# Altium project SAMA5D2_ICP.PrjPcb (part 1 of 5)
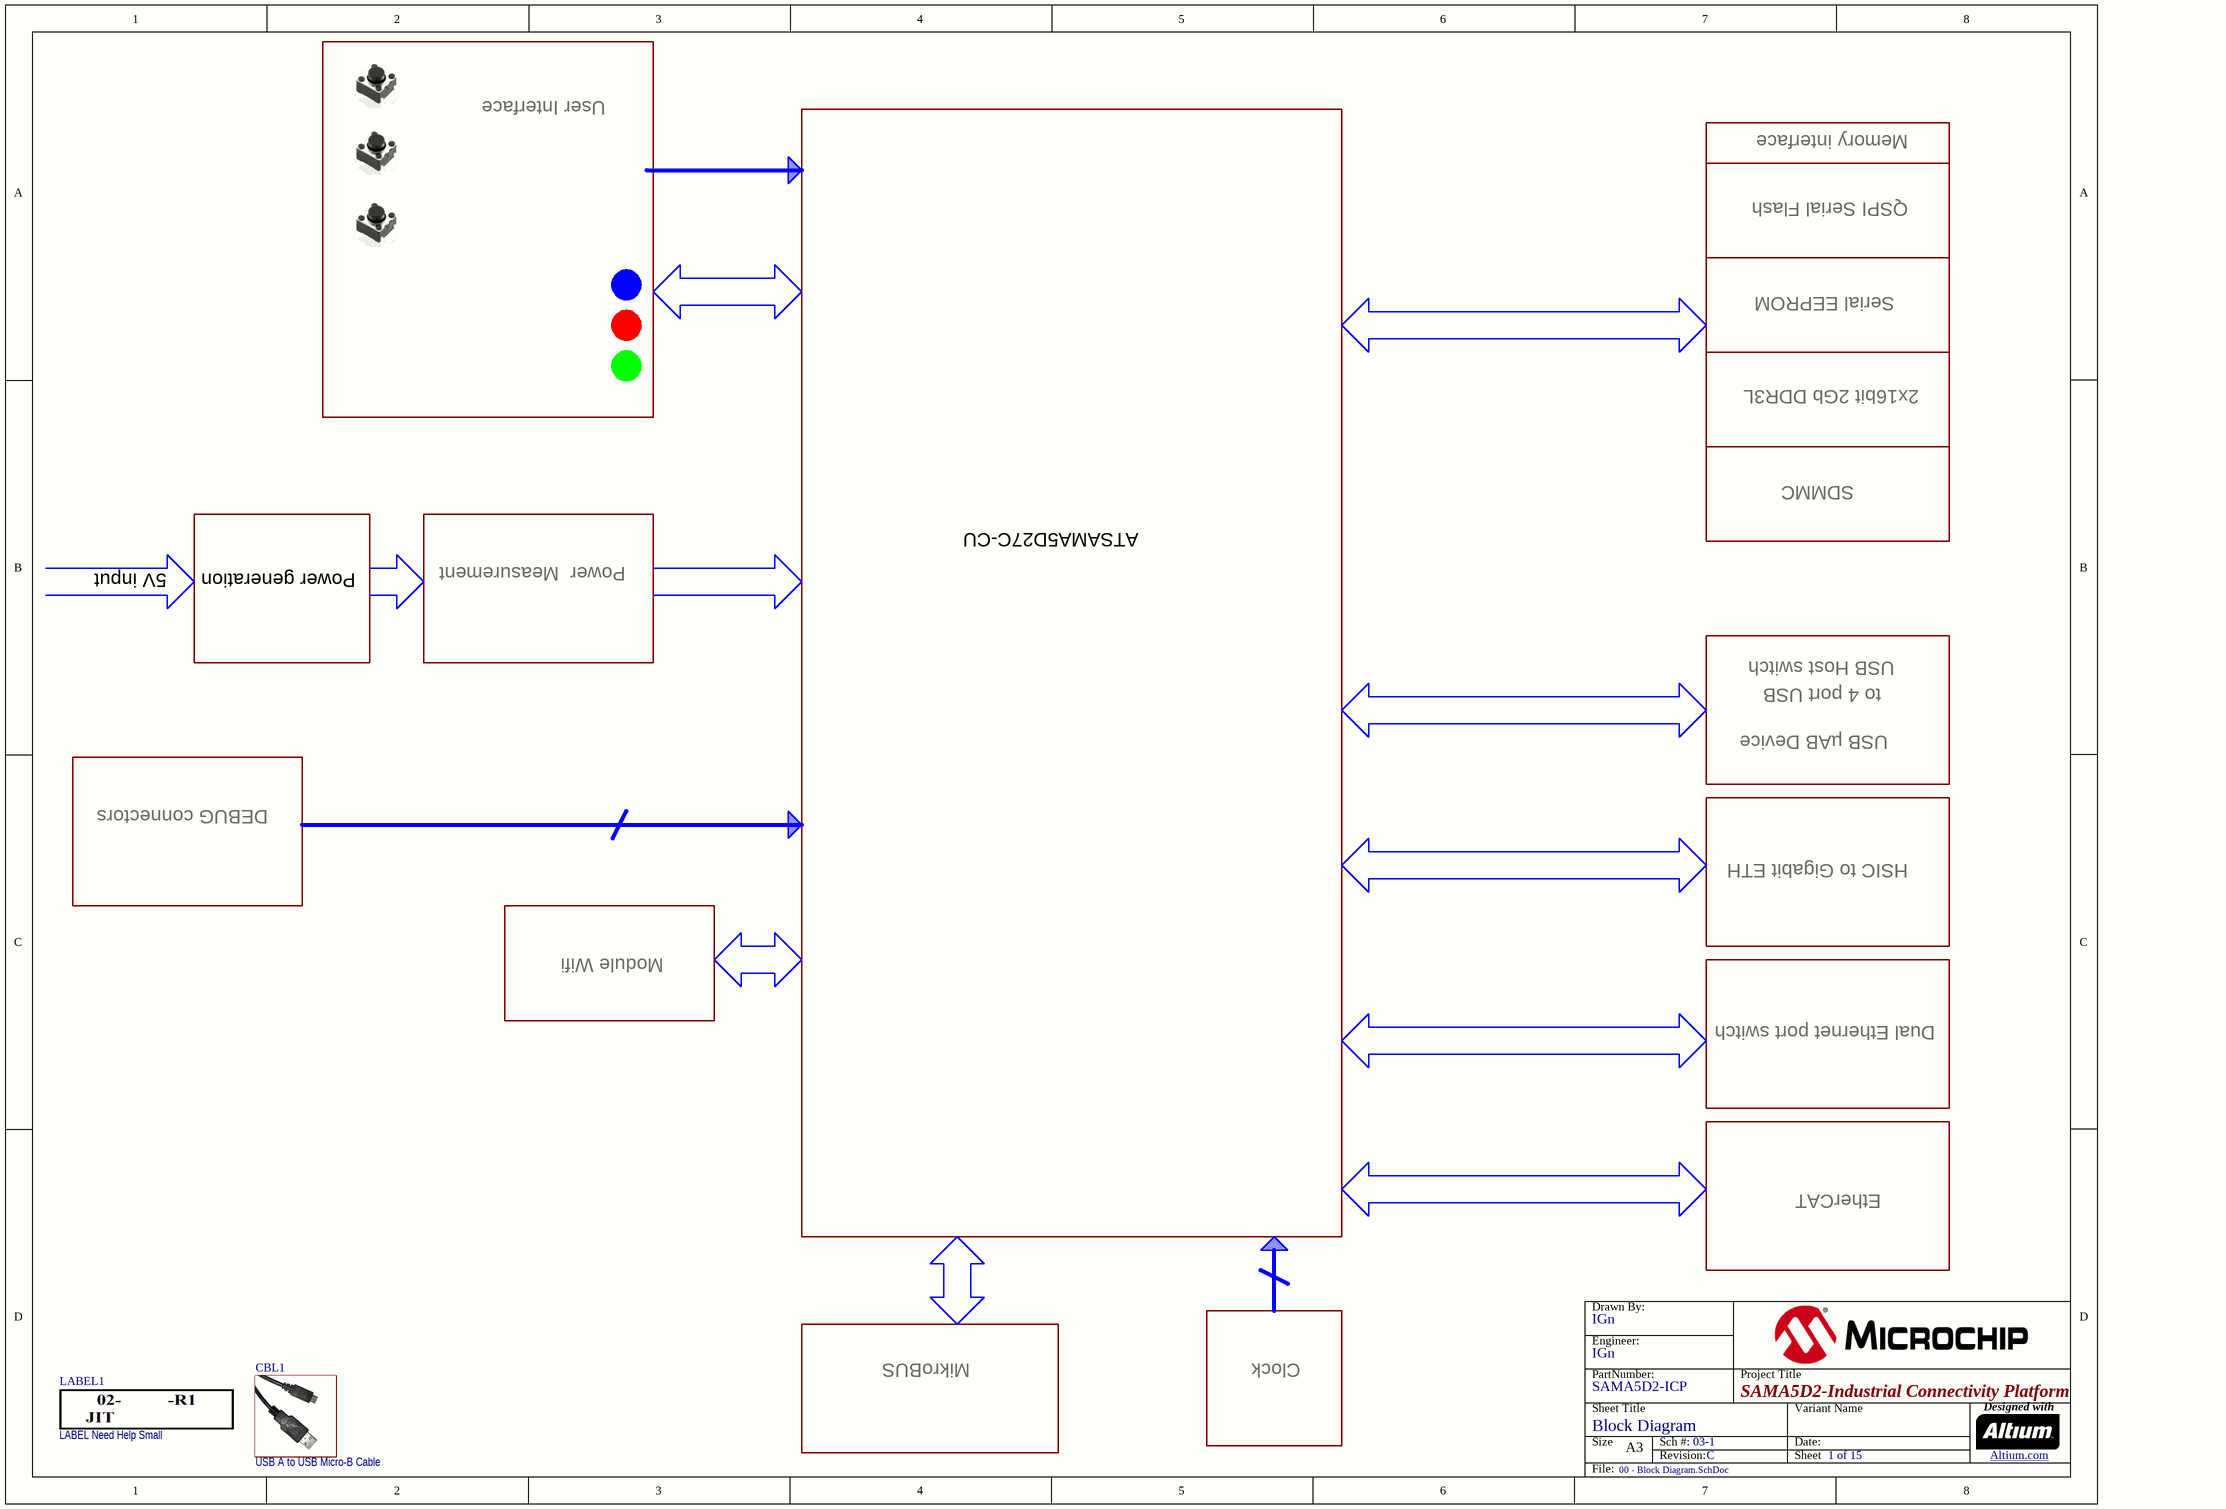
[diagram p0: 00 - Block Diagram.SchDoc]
ProjectBoardNumber: 1; ProjectDrawnBy: IGn; ProjectEngineer: IGn; ProjectPartNumber: SAMA5D2-ICP; ProjectRevisionART: C; ProjectRevisionASSY: C; ProjectRevisionFAB: C; ProjectRevisionSCH: C; ProjectTitle: SAMA5D2-Industrial Connectivity Platform
15 sheets, 727 parts. Net scope: global (net labels, ports and power ports of the same name join across sheets).
Board file: SAMA5D2_ICP.PcbDoc
Sheets:
  00 - Block Diagram.SchDoc
  01 - Power Supply.SchDoc
  02 - Power Measurement.SchDoc
  03 - SAMA5D2 - MPU.SchDoc
  04 - SAMA5D2 - DDR.SchDoc
  05 - SAMA5D2 - PIOs.SchDoc
  06 - USB.SchDoc
  07 - USB HSIC to Gb Ethernet.SchDoc
  08 - Ethernet switch.SchDoc
  09 - EtherCAT interface.SchDoc
  10 - CAN & WiFi BT.SchDoc
  11 - On Board Memories.SchDoc
  12 - Expansion connectors.SchDoc
  13 - User Command & Control.SchDoc
  14 - JLINK-OB Interface.SchDoc

## Sheet 00 - Block Diagram.SchDoc
size A3; CompanyName: Microchip Technology Inc.; Organization: Microchip Technology; Address1: 2355 West Chandler Blvd.; Address2: Chandler, AZ  85224; Address4: USA; DocumentNumber: 1; SheetNumber: 1; SheetTotal: 15; SheetTitle: Block Diagram

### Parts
(Parts that share a designator on the sheet are numbered #1, #2 ... from top to bottom, then left to right.)
?#1  (no value)  (graphical)
CBL1  USB A to USB Micro-B Cable  (mechanical)
LABEL1  value LABEL Need Help Small  [LABEL_Need_Help_Small]  (hidden comment: LABEL_Need_Help_Small)

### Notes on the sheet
- User Interface
- Memory interface
- QSPI Serial Flash
- Serial EEPROM
- 2x16bit 2Gb DDR3L
- SDMMC
- 5V input
- Power generation
- Power  Measurement
- ATSAMA5D27C-CU
- USB Host switch
- to 4 port USB
- USB µAB Device
- DEBUG connectors
- HSIC to Gigabit ETH
- Module Wifi
- Dual Ethernet port switch
- EtherCAT
- MikroBUS
- Clock

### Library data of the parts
?#1 = Title Block A3
CBL1 = CAB1020: Manufacturer 1: Assmann WSW Components; Manufacturer Part Number 1: AK67421-1; Description_: MECH HW CABLE USB Male A TO USB Male Micro-B 1M; Dev Tools Status: Design; Owner: Ilie Galan; Populated: MECH
LABEL1 = 08-00028: Description_: LABEL, ASSY W/REV LEVEL (SMALL MODULES) PER MTS-0002; Dev Tools Status: Production; Populated: MECH

## Sheet 01 - Power Supply.SchDoc
size B; CompanyName: Microchip Technology Inc.; Organization: Microchip Technology; Address1: 2355 West Chandler Blvd.; Address2: Chandler, AZ  85224; Address4: USA; DocumentNumber: 2; SheetNumber: 2; SheetTotal: 15; SheetTitle: Power Supply
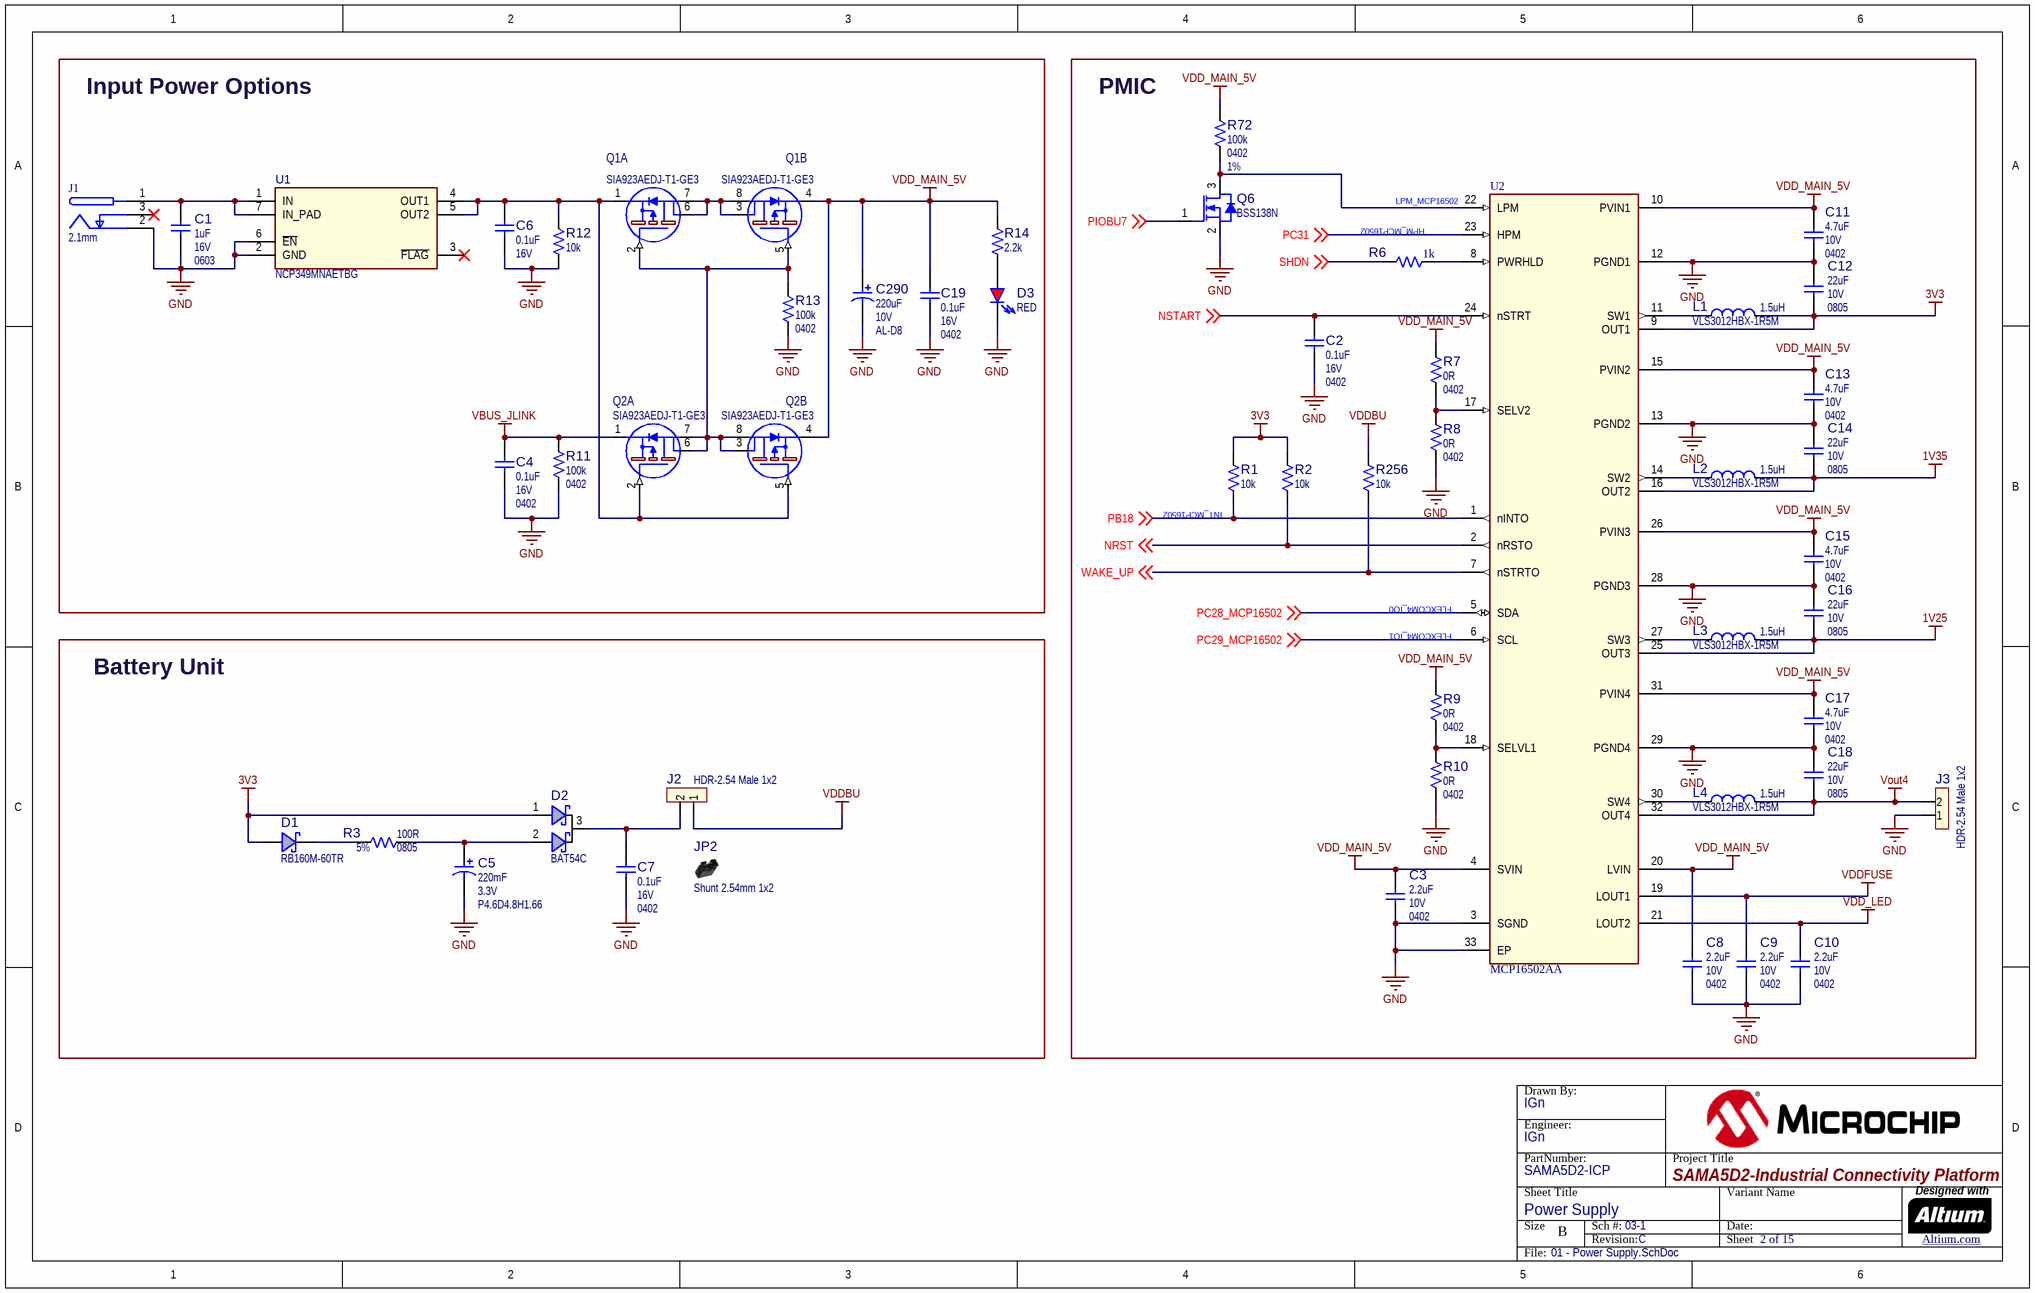
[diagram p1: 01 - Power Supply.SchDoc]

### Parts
(Parts that share a designator on the sheet are numbered #1, #2 ... from top to bottom, then left to right.)
?#2  (no value)  (graphical)
C1  value 1uF  Voltage: 16V  Package: 0603  [CAP_C_0603]  (hidden comment: Capacitor NP)
C2  value 0.1uF  Voltage: 16V  Package: 0402  [CAP_C_0402]  (hidden comment: Capacitor NP)
C3  value 2.2uF  Voltage: 10V  Package: 0402  [CAP_C_0402]  (hidden comment: Capacitor NP)
C4  value 0.1uF  Voltage: 16V  Package: 0402  [CAP_C_0402]  (hidden comment: Capacitor NP)
C5  value 220mF  Voltage: 3.3V  Package: P4.6D4.8H1.66  [CAP_SMD_ECH-U1C471JX5]  (hidden comment: Capacitor POL)
C6  value 0.1uF  Voltage: 16V  [CAP_C_0402]  (hidden comment: Capacitor NP)
C7  value 0.1uF  Voltage: 16V  Package: 0402  [CAP_C_0402]  (hidden comment: Capacitor NP)
C8  value 2.2uF  Voltage: 10V  Package: 0402  [CAP_C_0402]  (hidden comment: Capacitor NP)
C9  value 2.2uF  Voltage: 10V  Package: 0402  [CAP_C_0402]  (hidden comment: Capacitor NP)
C10  value 2.2uF  Voltage: 10V  Package: 0402  [CAP_C_0402]  (hidden comment: Capacitor NP)
C11  value 4.7uF  Voltage: 10V  Package: 0402  [CAP_C_0402]  (hidden comment: Capacitor NP)
C12  value 22uF  Voltage: 10V  Package: 0805  [CAP_C_0805]  (hidden comment: Capacitor NP)
C13  value 4.7uF  Voltage: 10V  Package: 0402  [CAP_C_0402]  (hidden comment: Capacitor NP)
C14  value 22uF  Voltage: 10V  Package: 0805  [CAP_C_0805]  (hidden comment: Capacitor NP)
C15  value 4.7uF  Voltage: 10V  Package: 0402  [CAP_C_0402]  (hidden comment: Capacitor NP)
C16  value 22uF  Voltage: 10V  Package: 0805  [CAP_C_0805]  (hidden comment: Capacitor NP)
C17  value 4.7uF  Voltage: 10V  Package: 0402  [CAP_C_0402]  (hidden comment: Capacitor NP)
C18  value 22uF  Voltage: 10V  Package: 0805  [CAP_C_0805]  (hidden comment: Capacitor NP)
C19  value 0.1uF  Voltage: 16V  Package: 0402  [CAP_C_0402]  (hidden comment: Capacitor NP)
C290  value 220uF  Voltage: 10V  Package: AL-D8  [CAP_AL_D8]  (hidden comment: Capacitor POL)
D1  value RB160M-60TR  [SOD-123FL]  (hidden comment: Diode Schottky)
D2  value BAT54C  [SOT-23-3]  (hidden comment: Diode Schottky Dual CK)
D3  value RED  [LED_0402_RED]  (hidden comment: LED_red)
J1  value 2.1mm  [CON_JACK_POWER_TH_RA_MPD_EJ508A]  (hidden comment: CON JACK 2C 3P SPST)
J2  value HDR-2.54 Male 1x2  [HDR_M_2.54_1x2]  (hidden comment: Header 1x2)
J3  value HDR-2.54 Male 1x2  [HDR_M_2.54_1x2]  (hidden comment: Header 1x2)
JP2  value Shunt 2.54mm 1x2  [Jumper_Mechanical]  (hidden comment: Jumper Mechanical)  (mechanical)
L1  value 1.5uH  Manufacturer Part Number 1: VLS3012HBX-1R5M  [IND_C_1212]  (hidden comment: Inductor)
L2  value 1.5uH  Manufacturer Part Number 1: VLS3012HBX-1R5M  [IND_C_1212]  (hidden comment: Inductor)
L3  value 1.5uH  Manufacturer Part Number 1: VLS3012HBX-1R5M  [IND_C_1212]  (hidden comment: Inductor)
L4  value 1.5uH  Manufacturer Part Number 1: VLS3012HBX-1R5M  [IND_C_1212]  (hidden comment: Inductor)
Q1  SIA923AEDJ-T1-GE3  [SiA923AEDJ PPAK_SC70_6L]  (parts A,B of 2)
Q2  SIA923AEDJ-T1-GE3  [SiA923AEDJ PPAK_SC70_6L]  (parts A,B of 2)
Q6  value BSS138N  [SOT-23-3]  (hidden comment: Transistor MOS-N GSD)
R1  value 10k  [RES_C_0402]  (hidden comment: Resistor)
R2  value 10k  [RES_C_0402]  (hidden comment: Resistor)
R3  value 100R  Package: 0805  Tolerance: 5%  [RES_C_0805]  (hidden comment: Resistor)
R6  value 1k  [RES_C_0603]  (hidden comment: Resistor)
R7  value 0R  Package: 0402  [RES_C_0402]  (hidden comment: Resistor)
R8  value 0R  Package: 0402  [RES_C_0402]  (hidden comment: Resistor)
R9  value 0R  Package: 0402  [RES_C_0402]  (hidden comment: Resistor)
R10  value 0R  Package: 0402  [RES_C_0402]  (hidden comment: Resistor)
R11  value 100k  Package: 0402  [RES_C_0402]  (hidden comment: Resistor)
R12  value 10k  [RES_C_0402]  (hidden comment: Resistor)
R13  value 100k  Package: 0402  [RES_C_0402]  (hidden comment: Resistor)
R14  value 2.2k  [RES_C_0603]  (hidden comment: Resistor)
R72  value 100k  Package: 0402  Tolerance: 1%  [RES_C_0402]  (hidden comment: Resistor)
R256  value 10k  [RES_C_0402]  (hidden comment: Resistor)
U1  value NCP349MNAETBG  [DFN-6_2x1.6_EP0.4x0.35]  (hidden comment: NCP349 DFN-6)
U2  MCP16502AA  [QFN-32_5X5_EP3.7X3.7]

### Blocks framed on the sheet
Input Power Options: C1 C4 C6 C19 C290 D3 J1 Q1 Q2 R11-R14 U1
PMIC: C2 C3 C8-C18 J3 L1-L4 Q6 R1 R2 R6-R10 R72 R256 U2
Battery Unit: C5 C7 D1 D2 J2 JP2 R3

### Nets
1V25: C16.1 L3.2(F) U2.25(OUT3)
1V35: C14.1 L2.2(F) U2.16(OUT2)
3V3: C12.1 D1.1(A) D2.1(A) L1.2(F) R1.2 R2.2 U2.9(OUT1)
GND: C1.1 C2.1 C3.1 C4.1 C5.2 C6.1 C7.1 C8.1 C9.1 C10.1 C11.1 C12.2 C13.1 C14.2 C15.1 C16.2 C17.1 C18.2 C19.1 C290.2 D3.2(K) J1.2(COM) J3.1 Q6.2(S) R8.1 R10.1 R11.2 R12.1 R13.2 U1.2(GND) U1.6(~{EN}) U2.3(SGND) U2.12(PGND1) U2.13(PGND2) U2.28(PGND3) U2.29(PGND4) U2.33(EP)
VBUS_JLINK: C4.2 Q2.1(S1) R11.1
VDD_LED: C10.2 U2.21(LOUT2)
VDD_MAIN_5V: C3.2 C8.2 C11.2 C13.2 C15.2 C17.2 C19.2 C290.1 Q1.4(S2) Q2.4(S2) R7.2 R9.2 R14.2 R72.2 U2.4(SVIN) U2.10(PVIN1) U2.15(PVIN2) U2.20(LVIN) U2.26(PVIN3) U2.31(PVIN4)
VDDBU: J2.1 R256.2
VDDFUSE: C9.2 U2.19(LOUT1)
Vout4: C18.1 J3.2 L4.2(F) U2.32(OUT4)
NRST: R2.1 U2.2(nRSTO) ; off-sheet NRST
NSTART: C2.2 U2.24(nSTRT) ; off-sheet NSTART
PB18: R1.1 U2.1(nINTO) ; off-sheet PB18
PC28_MCP16502: U2.5(SDA) ; off-sheet PC28_MCP16502
PC29_MCP16502: U2.6(SCL) ; off-sheet PC29_MCP16502
PC31: U2.23(HPM) ; off-sheet PC31
PIOBU7: Q6.1(G) ; off-sheet PIOBU7
SHDN: R6.1 ; off-sheet SHDN
WAKE_UP: R256.1 U2.7(nSTRTO) ; off-sheet WAKE_UP
NetC1_2: C1.2 J1.1(PLUS) U1.1(IN) U1.7(IN_PAD)
NetC5_1: C5.1 D2.2(A) R3.2
NetC6_2: C6.2 Q1.1(S1) Q2.2(G1) Q2.5(G2) R12.2 U1.4(OUT1) U1.5(OUT2)
NetC7_2: C7.2 D2.3(KK) J2.2
NetD1_2: D1.2(K) R3.1
NetD3_1: D3.1(A) R14.1
NetL1_1: L1.1(S) U2.11(SW1)
NetL2_1: L2.1(S) U2.14(SW2)
NetL3_1: L3.1(S) U2.27(SW3)
NetL4_1: L4.1(S) U2.30(SW4)
NetQ1_2: Q1.2(G1) Q1.5(G2) Q2.3(D2) Q2.6(D1) Q2.7(D1_2) Q2.8(D2_2) R13.1
NetQ1_3: Q1.3(D2) Q1.6(D1) Q1.7(D1_2) Q1.8(D2_2)
NetQ6_3: Q6.3(D) R72.1 U2.22(LPM)
NetR6_2: R6.2 U2.8(PWRHLD)
NetR7_1: R7.1 R8.2 U2.17(SELV2)
NetR9_1: R9.1 R10.2 U2.18(SELVL1)

Not connected (* = marked no-connect by the designer): J1 3(SWITCH)*; U1 3(~{FLAG})*

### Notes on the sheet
- LPM_MCP16502
- (near R6) HPM_MCP16502
- (near R1) INT_MCP16502
- (near U2) FLEXCOM4_IO0
- FLEXCOM4_IO1

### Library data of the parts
?#2 = Title Block B
C1 = CAP0265: Capacitor; Manufacturer 1: AVX; Manufacturer Part Number 1: 0603YD105KAT2A; Description_: CAP CER 1uF 16V 10% X5R SMD 0603; Dev Tools Status: Production; Tolerance: 10%; Temperature Coeffcient: X5R; Type: Ceramic; Populated: Yes
C2 C4 C6 C7 C19 = CAP1033: Capacitor; Manufacturer 1: Murata; Manufacturer Part Number 1: GRM155R71C104KA88D; Description_: CAP CER 0.1uF 16V 10% X7R SMD 0402; Dev Tools Status: Production; Tolerance: 10%; Temperature Coeffcient: X7R; Type: Ceramic; Owner: Sompoch Loboonlert; Populated: Yes
C3 C8-C10 = CAP1468: Capacitor; Manufacturer 1: TDK Corporation; Manufacturer Part Number 1: C1005X7S1A225K050BC; Description_: CAP CER 2.2uF 10V 10% X7S SMD 0402; Dev Tools Status: Production; Tolerance: 10%; Temperature Coeffcient: X7S; Type: Ceramic; Owner: Sorin Stanoaia; Populated: YES
C5 = CAP1487: Capacitor; Manufacturer 1: Elna America; Manufacturer Part Number 1: DSK-3R3H224U-HL; Description_: CAP SUPERCAP 220mF 3.3V 80% SMD P4.6D4.8H1.66; Dev Tools Status: Design; Tolerance: -20%, +80%; Type: Supercap; Owner: Tad Ahlvers; Populated: YES
C11 C13 C15 C17 = CAP1684: Capacitor; Manufacturer 1: TDK Corporation; Manufacturer Part Number 1: C1005X5R1A475K050BC; Description_: CAP CER 4.7uF 10V 10% X5R SMD 0402; Dev Tools Status: Production; Tolerance: 10%; Temperature Coeffcient: X5R; Type: Ceramic; Owner: Jesus Aviles; Populated: YES
C12 C14 C16 C18 = CAP1645: Capacitor; Manufacturer 1: Taiyo Yuden; Manufacturer Part Number 1: LMK212BJ226MG-T; Description_: CAP CER 22uF 10V 20% X5R SMD 0805; Dev Tools Status: Production; Tolerance: 20%; Temperature Coeffcient: X5R; Type: Ceramic; Owner: Razvan Cristescu; Populated: YES
C290 = CAP0546: Capacitor; Manufacturer 1: Panasonic; Manufacturer Part Number 1: EEE-1AA221XP; Description_: CAP ALU 220uF 10V 20% SMD D8; Dev Tools Status: Production; Tolerance: 20%; Type: Aluminum; Populated: Yes
D1 = DIODE1357: DIO SCTKY RB160M-60TR 550mV 1A 60V SMD SOD-123F; Manufacturer 1: Rohm Semiconductor; Dev Tools Status: Production; Power: 1W; Reverse Current: 50uA; Reverse Recovery Time: 11.7ns; Owner: Dragos Danaila; Populated: YES
D2 = DIODE0101: Manufacturer 1: Fairchild; Description_: DIO SCTKYARR BAT54C 800mV 200mA 30V SOT-23-3; Dev Tools Status: Production; Type: Schottky Array; Forward Current: 200mA; Power: 290mW; Reverse Current: 2uA; Reverse Voltage: 30V; Populated: Yes
D3 = DIODE1426: LED; Manufacturer 1: Rohm Semiconductor; Manufacturer Part Number 1: SML-P11VTT86; Description_: DIO LED RED 1.8V 1mA 4mcd CLEAR SMD 0402; Dev Tools Status: Design; Type: LED Single; Forward Current: 1mA; Power: 50mW; Reverse Current: 10uA; Reverse Voltage: 5V; Owner: Ilie Galan; Populated: YES
J1 = CON1560: Manufacturer 1: MPD (Memory Protection Devices); Manufacturer Part Number 1: EJ508A; Description_: CON POWER 2.1mm 5.5mm Switch Slotted TH R/A; Dev Tools Status: Production; Populated: YES; Owner: Mark Loper
J2 = CON1108: Manufacturer 1: FCI; Manufacturer Part Number 1: 77311-118-02LF; Description_: CON HDR-2.54 Male 1x2 Gold 5.84MH TH VERT; Dev Tools Status: Production; Owner: Bogdan P (M91398); Populated: Yes
J3 = CON1108: Manufacturer 1: FCI; Manufacturer Part Number 1: 77311-118-02LF; Description_: CON HDR-2.54 Male 1x2 Gold 5.84MH TH VERT; Dev Tools Status: Production; Owner: Bogdan P (M91398); Populated: DNP
JP2 = HW1006: Manufacturer 1: 3M; Manufacturer Part Number 1: 969102-0000-DA; MCHP-ID: HW1006; Description_: MECH HW JUMPER 2.54mm 1x2; Dev Tools Status: Production; Owner: Mike Ragsdale; Populated: MECH
L1-L4 = IND1590: Manufacturer 1: TDK Corporation; Description_: INDUCTOR 1.5UH 4.19A 20% SMD 1212(3030); Dev Tools Status: Design; Owner: Ilie Galan; DCR: 0.067R; Saturation Current: 4.41A; RMS Current: 4.19A; Test Frequency: 1MHz; Populated: YES
Q1 Q2 = TRA1245: Manufacturer 1: Vishay Siliconix; Description_: TRANS FET DUAL P+P SIA923AEDJ -20V -4.5A 7.8W SC70-6L; Dev Tools Status: Design; Type: FET; Current: -4.5A; Drain to Source Voltage: -20V; Gate to Source Voltage: 900mV; Power: 7.8W; Owner: Dragos Danaila; Populated: YES
Q6 = TRA1223: Transistor MOS; Manufacturer 1: Infineon Technologies; Manufacturer Part Number 1: BSS138NH6327XTSA2; Description_: TRANS FET N-CH BSS138N 60V 230mA SOT23-3; Dev Tools Status: Production; Type: FET; Current: 230mA; Drain to Source Voltage: 60V; Gate to Source Voltage: 20V; Power: 0.36W; Owner: Dragos Danaila; Populated: YES
R1 R2 R12 = RSMT1019: Manufacturer 1: Panasonic; Manufacturer Part Number 1: ERJ-2RKF1002X; Tolerance: 1%; Description_: RES TKF 10k 1% 1/10W SMD 0402; Dev Tools Status: Production; Voltage: 50V; Temperature Coeffcient: 100ppm/C; Power: 1/10W; Owner: Brent Lanphear; Populated: Yes
R3 = RSMT0021: Manufacturer 1: Stackpole Electronics Inc.; Manufacturer Part Number 1: RMCF0805JT100R; Description_: RES TKF 100R 5% 1/8W SMD 0805; Dev Tools Status: Production; Voltage: 150V; Temperature Coeffcient: 100ppm/C; Power: 1/8W; Populated: Yes
R6 = RSMT0138: Manufacturer 1: Panasonic; Manufacturer Part Number 1: ERJ-3EKF1001V; Tolerance: 1%; Description_: RES TKF 1k 1% 1/10W SMD 0603; Dev Tools Status: Production; Voltage: 75V; Temperature Coeffcient: 100ppm/C; Power: 1/10W; Populated: Yes
R7-R10 = RSMT1040: Manufacturer 1: Yageo; Manufacturer Part Number 1: RC0402JR-070RL; Description_: RES TKF 0R 1/16W SMD 0402; Dev Tools Status: Production; Power: 1/16W; Owner: Sompoch Loboonlert; Populated: DNP
R11 R13 = RES1011: Manufacturer 1: Panasonic; Manufacturer Part Number 1: ERJ-2RKF1003X; Tolerance: 1%; Description_: RES TKF 100k 1% 1/10W SMD 0402; Dev Tools Status: Production; Voltage: 50V; Temperature Coeffcient: 100ppm/C; Power: 1/10W; Owner: Tad Ahlvers; Populated: YES
R14 = RES1130: Manufacturer 1: Panasonic; Manufacturer Part Number 1: ERJ-3EKF2201V; Tolerance: 1%; Description_: RES TKF 2.2k 1% 1/10W SMD 0603; Dev Tools Status: Production; Voltage: 75V; Temperature Coeffcient: 100ppm/C; Power: 1/10W; Owner: Bogdan P (M91398); Populated: Yes
R72 = RES1011: Manufacturer 1: Panasonic; Manufacturer Part Number 1: ERJ-2RKF1003X; Description_: RES TKF 100k 1% 1/10W SMD 0402; Dev Tools Status: Production; Voltage: 50V; Temperature Coeffcient: 100ppm/C; Power: 1/10W; Owner: Tad Ahlvers; Populated: YES
R256 = RSMT1019: Manufacturer 1: Panasonic; Manufacturer Part Number 1: ERJ-2RKF1002X; Tolerance: 1%; Description_: RES TKF 10k 1% 1/10W SMD 0402; Dev Tools Status: Production; Voltage: 50V; Temperature Coeffcient: 100ppm/C; Power: 1/10W; Owner: Brent Lanphear; Populated: YES
U1 = IC1481: Manufacturer 1: ON Semiconductor; MCHP-ID: IC1481; Description_: IC POWER NCP349MNAETBG Power Supply Controller Overvoltage Protection DFN-6; Dev Tools Status: Design; Vin: 1.2 V to 28 V; Owner: Ciprian Abramov; Populated: YES
U2 = MCP16502 QFN-32: QFN-32; Manufacturer 1: Microchip; Manufacturer Part Number 1: MCP16502AA-E/S8; Description_: PMIC; Populated: YES

## Sheet 02 - Power Measurement.SchDoc
size B; CompanyName: Microchip Technology Inc.; Organization: Microchip Technology; Address1: 2355 West Chandler Blvd.; Address2: Chandler, AZ  85224; Address4: USA; DocumentNumber: 3; SheetNumber: 3; SheetTotal: 15; SheetTitle: Power Measurement
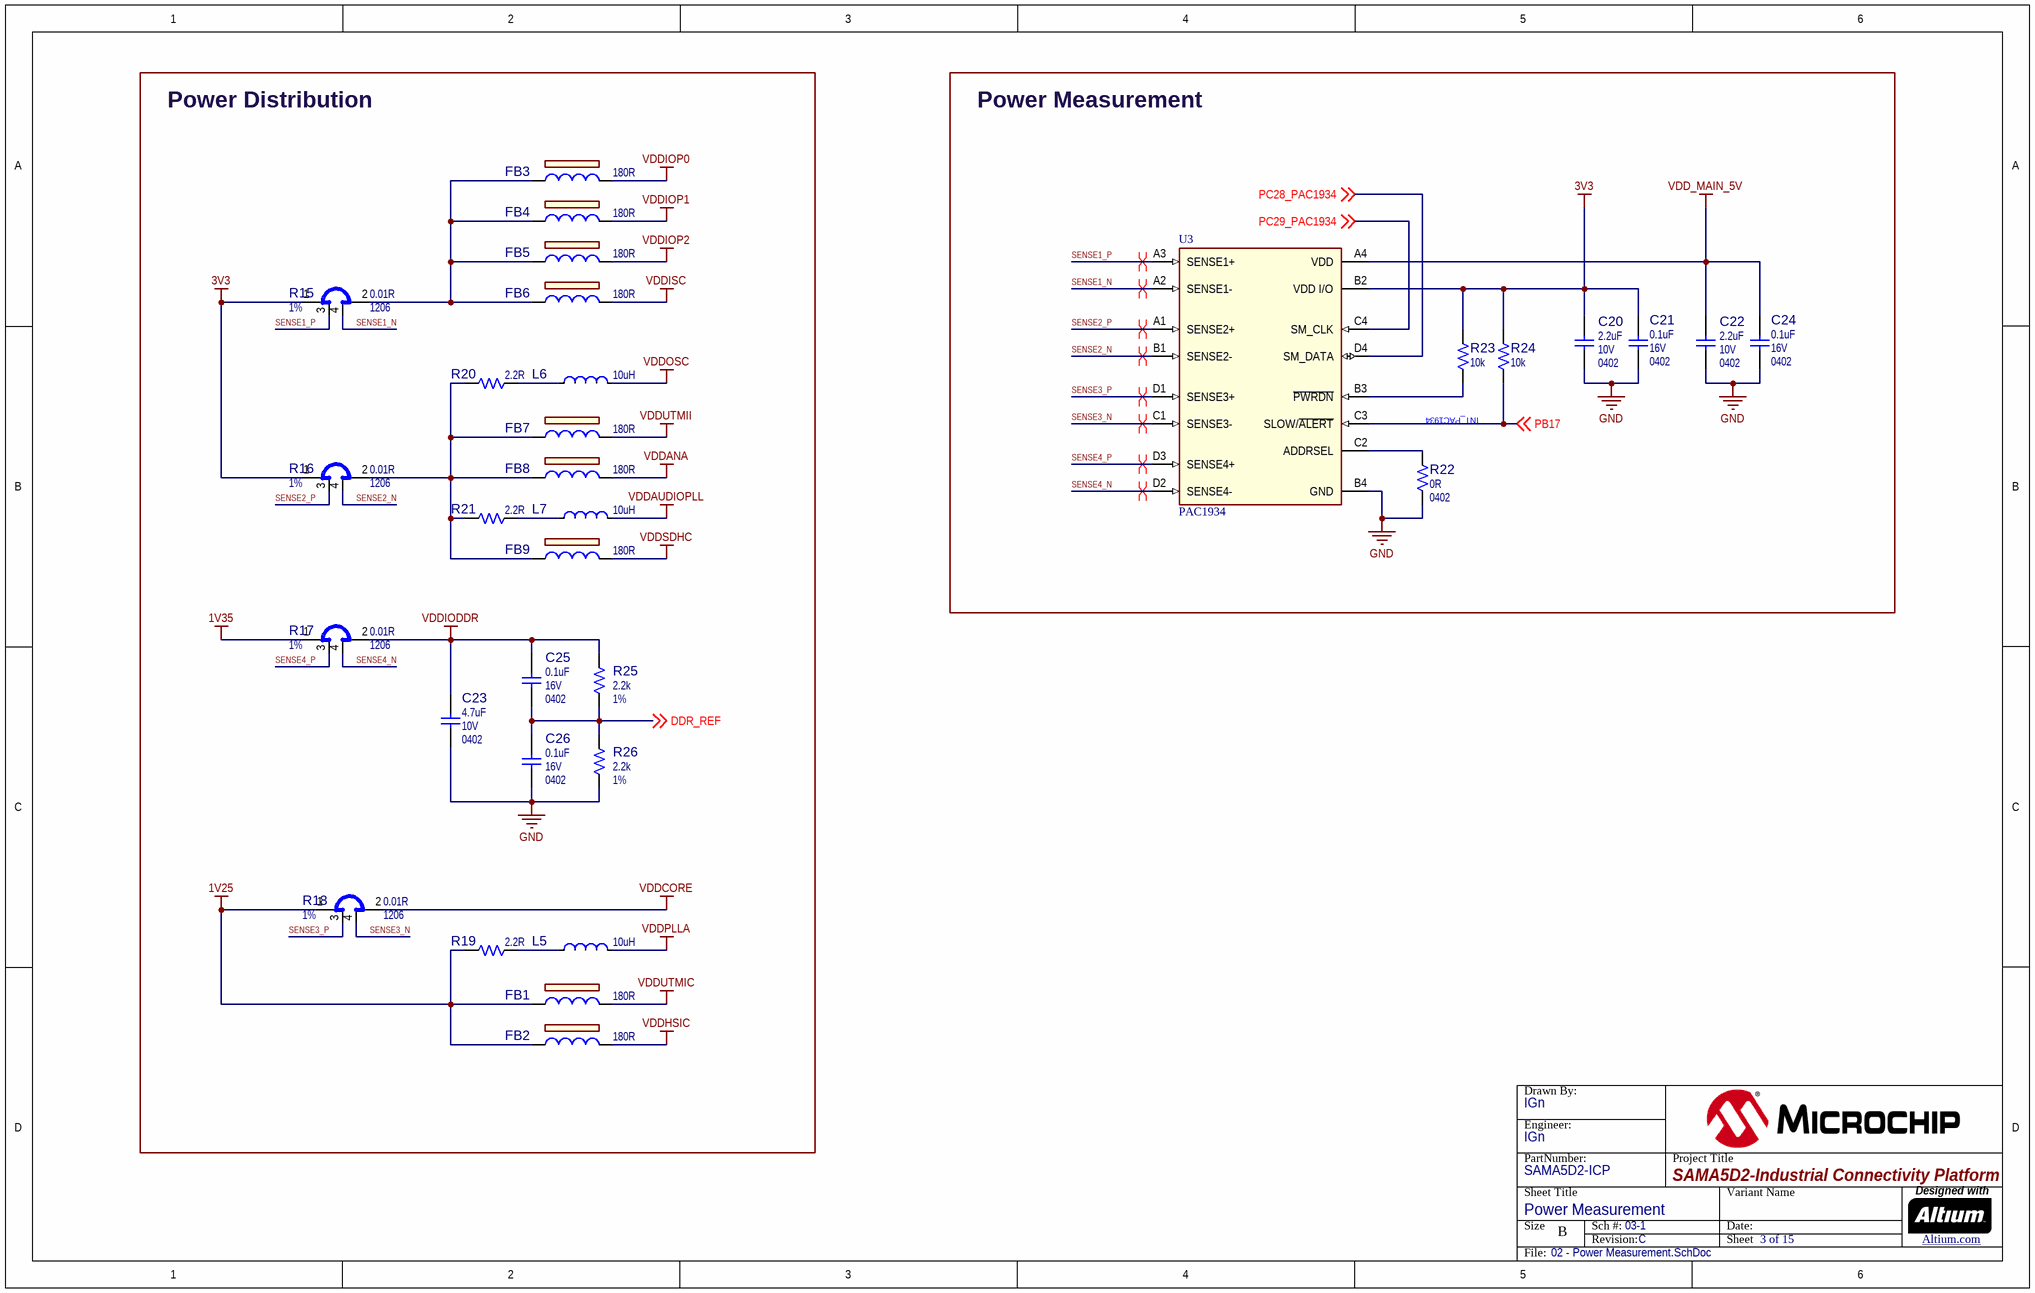
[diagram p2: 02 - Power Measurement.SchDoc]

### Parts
(Parts that share a designator on the sheet are numbered #1, #2 ... from top to bottom, then left to right.)
?#3  (no value)  (graphical)
C20  value 2.2uF  Voltage: 10V  Package: 0402  [CAP_C_0402]  (hidden comment: Capacitor NP)
C21  value 0.1uF  Voltage: 16V  Package: 0402  [CAP_C_0402]  (hidden comment: Capacitor NP)
C22  value 2.2uF  Voltage: 10V  Package: 0402  [CAP_C_0402]  (hidden comment: Capacitor NP)
C23  value 4.7uF  Voltage: 10V  Package: 0402  [CAP_C_0402]  (hidden comment: Capacitor NP)
C24  value 0.1uF  Voltage: 16V  Package: 0402  [CAP_C_0402]  (hidden comment: Capacitor NP)
C25  value 0.1uF  Voltage: 16V  Package: 0402  [CAP_C_0402]  (hidden comment: Capacitor NP)
C26  value 0.1uF  Voltage: 16V  Package: 0402  [CAP_C_0402]  (hidden comment: Capacitor NP)
FB1  value 180R  [IND_C_0603]  (hidden comment: Ferrite Bead)
FB2  value 180R  [IND_C_0603]  (hidden comment: Ferrite Bead)
FB3  value 180R  [IND_C_0603]  (hidden comment: Ferrite Bead)
FB4  value 180R  [IND_C_0603]  (hidden comment: Ferrite Bead)
FB5  value 180R  [IND_C_0603]  (hidden comment: Ferrite Bead)
FB6  value 180R  [IND_C_0603]  (hidden comment: Ferrite Bead)
FB7  value 180R  [IND_C_0603]  (hidden comment: Ferrite Bead)
FB8  value 180R  [IND_C_0603]  (hidden comment: Ferrite Bead)
FB9  value 180R  [IND_C_0603]  (hidden comment: Ferrite Bead)
L5  value 10uH  [IND_C_0603]  (hidden comment: Inductor)
L6  value 10uH  [IND_C_0603]  (hidden comment: Inductor)
L7  value 10uH  [IND_C_0603]  (hidden comment: Inductor)
R15  value 0.01R  Package: 1206  Tolerance: 1%  [RES_C_1206_SHUNT]  (hidden comment: Shunt 4 Pin)
R16  value 0.01R  Package: 1206  Tolerance: 1%  [RES_C_1206_SHUNT]  (hidden comment: Shunt 4 Pin)
R17  value 0.01R  Package: 1206  Tolerance: 1%  [RES_C_1206_SHUNT]  (hidden comment: Shunt 4 Pin)
R18  value 0.01R  Package: 1206  Tolerance: 1%  [RES_C_1206_SHUNT]  (hidden comment: Shunt 4 Pin)
R19  value 2.2R  [RES_C_0603]  (hidden comment: Resistor)
R20  value 2.2R  [RES_C_0603]  (hidden comment: Resistor)
R21  value 2.2R  [RES_C_0603]  (hidden comment: Resistor)
R22  value 0R  Package: 0402  [RES_C_0402]  (hidden comment: Resistor)
R23  value 10k  [RES_C_0402]  (hidden comment: Resistor)
R24  value 10k  [RES_C_0402]  (hidden comment: Resistor)
R25  value 2.2k  Tolerance: 1%  [RES_C_0603]  (hidden comment: Resistor)
R26  value 2.2k  Tolerance: 1%  [RES_C_0603]  (hidden comment: Resistor)
U3  value PAC1934  [WLCSP-16_2.215X2.16]  (hidden comment: PAC1934 WLCSP-16)

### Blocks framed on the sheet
Power Distribution: C23 C25 C26 FB1-FB9 L5-L7 R15-R21 R25 R26
Power Measurement: C20-C22 C24 R22-R24 U3

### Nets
1V25: FB1.1 FB2.1 R18.1 R19.1
1V35: R17.1
3V3: C20.2 C21.2 R15.1 R16.1 R23.2 R24.2 U3.B2(VDD_I/O)
GND: C20.1 C21.1 C22.1 C23.1 C24.1 C26.1 R22.1 R26.1 U3.B4(GND)
VDD_MAIN_5V: C22.2 C24.2 U3.A4(VDD)
VDDANA: FB8.2
VDDAUDIOPLL: L7.2(F)
VDDCORE: R18.2
VDDHSIC: FB2.2
VDDIODDR: C23.2 C25.2 R17.2 R25.2
VDDIOP0: FB3.2
VDDIOP1: FB4.2
VDDIOP2: FB5.2
VDDISC: FB6.2
VDDOSC: L6.2(F)
VDDPLLA: L5.2(F)
VDDSDHC: FB9.2
VDDUTMIC: FB1.2
VDDUTMII: FB7.2
DDR_REF: C25.1 C26.2 R25.1 R26.2 ; off-sheet DDR_REF
PB17: R24.1 U3.C3(SLOW/~{ALERT}) ; off-sheet PB17
PC28_PAC1934: U3.D4(SM_DATA) ; off-sheet PC28_PAC1934
PC29_PAC1934: U3.C4(SM_CLK) ; off-sheet PC29_PAC1934
SENSE1_N: R15.4 U3.A2(SENSE1-)
SENSE1_P: R15.3 U3.A3(SENSE1+)
SENSE2_N: R16.4 U3.B1(SENSE2-)
SENSE2_P: R16.3 U3.A1(SENSE2+)
SENSE3_N: R18.4 U3.C1(SENSE3-)
SENSE3_P: R18.3 U3.D1(SENSE3+)
SENSE4_N: R17.4 U3.D2(SENSE4-)
SENSE4_P: R17.3 U3.D3(SENSE4+)
NetFB3_1: FB3.1 FB4.1 FB5.1 FB6.1 R15.2
NetFB7_1: FB7.1 FB8.1 FB9.1 R16.2 R20.1 R21.1
NetL5_1: L5.1(S) R19.2
NetL6_1: L6.1(S) R20.2
NetL7_1: L7.1(S) R21.2
NetR22_2: R22.2 U3.C2(ADDRSEL)
NetR23_1: R23.1 U3.B3(~{PWRDN})

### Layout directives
differential pair: SENSE1_N, SENSE1_P, SENSE2_N, SENSE2_P, SENSE3_N, SENSE3_P, SENSE4_N, SENSE4_P

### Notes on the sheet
- INT_PAC1934

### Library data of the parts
?#3 = Title Block B
C20 C22 = CAP1468: as C3 on sheet 01 - Power Supply
C21 C24-C26 = CAP1033: as C2 on sheet 01 - Power Supply
C23 = CAP1684: as C11 on sheet 01 - Power Supply
FB1-FB9 = IND1453: FERRITE 180R 1.5A SMD 0603; Manufacturer 1: Murata Electronics North America; Manufacturer Part Number 1: BLM18PG181SN1D; Dev Tools Status: Production; Owner: Dragos Danaila; DCR: 0.09R; Test Frequency: 100MHz; Populated: YES
L5-L7 = IND1213: Manufacturer 1: TDK Corporation; Manufacturer Part Number 1: MLZ1608N100LT000; Description_: INDUCTOR 10uH 600mA 20% SMD 0603; Dev Tools Status: Design; Owner: Jamus Griego; Populated: YES
R15-R18 = RSMT1231: Shunt; Manufacturer 1: Yageo; Manufacturer Part Number 1: PF1206FRF070R01L; Description_: RES SHUNT 0.01R 1% 1/4W 1206; Dev Tools Status: Design; Voltage: 50mV; Temperature Coeffcient: 100ppm/C; Current: 5A; Power: 1/4W; Owner: Dragos Danaila; Populated: YES
R19-R21 = RSMT1138: Manufacturer 1: Stackpole Electronics Inc; Manufacturer Part Number 1: RMCF0603JT2R20; Description_: RES TKF 2.2R 5% 1/10W SMD 0603; Dev Tools Status: Design; Owner: Jamus Griego; Populated: YES
R22 = RSMT1040: Manufacturer 1: Yageo; Manufacturer Part Number 1: RC0402JR-070RL; Description_: RES TKF 0R 1/16W SMD 0402; Dev Tools Status: Production; Power: 1/16W; Owner: Sompoch Loboonlert; Populated: YES
R23 R24 = RSMT1019: as R1 on sheet 01 - Power Supply
R25 R26 = RES1130: Manufacturer 1: Panasonic; Manufacturer Part Number 1: ERJ-3EKF2201V; Description_: RES TKF 2.2k 1% 1/10W SMD 0603; Dev Tools Status: Production; Voltage: 75V; Temperature Coeffcient: 100ppm/C; Power: 1/10W; Owner: Bogdan P (M91398); Populated: Yes
U3 = MIC7499: Manufacturer 1: Microchip Technology; Manufacturer Part Number 1: PAC1934T-I/J6CX; Description_: MCHP ANALOG POWER CURRENT SENSE MONITOR PAC1934T-I/J6CX WLCSP-16; Dev Tools Status: Production; Owner: Jose Garcia; Populated: YES

## Sheet 03 - SAMA5D2 - MPU.SchDoc
size B; CompanyName: Microchip Technology Inc.; Organization: Microchip Technology; Address1: 2355 West Chandler Blvd.; Address2: Chandler, AZ  85224; Address4: USA; DocumentNumber: 4; SheetNumber: 4; SheetTotal: 15; SheetTitle: SAMA5D2 - MPU
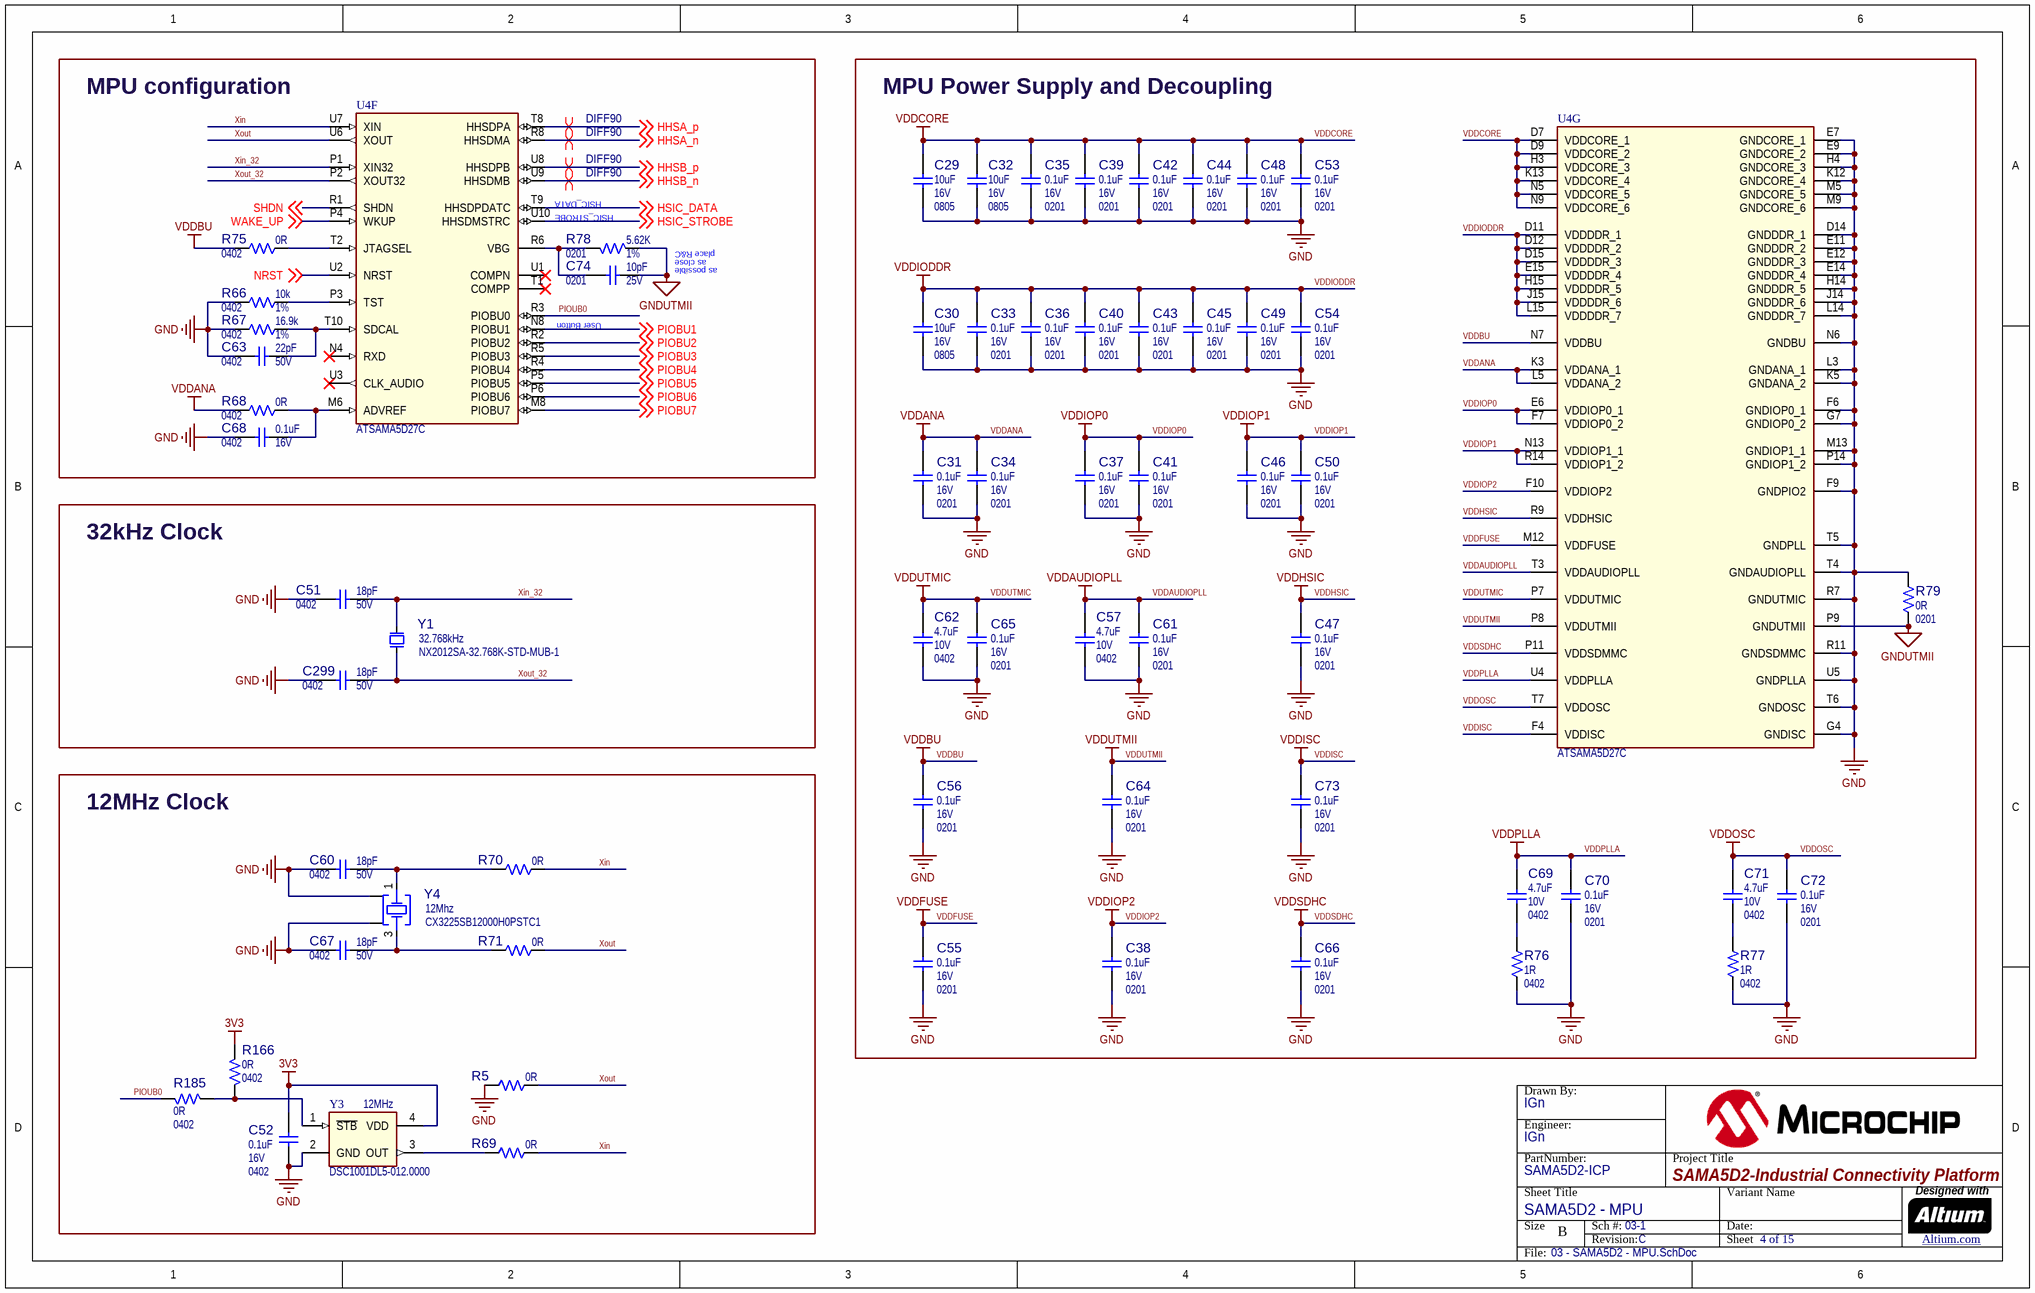
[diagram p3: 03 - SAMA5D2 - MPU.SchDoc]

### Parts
(Parts that share a designator on the sheet are numbered #1, #2 ... from top to bottom, then left to right.)
?#4  (no value)  (graphical)
C29  value 10uF  Voltage: 16V  Package: 0805  [CAP_C_0805]  (hidden comment: Capacitor NP)
C30  value 10uF  Voltage: 16V  Package: 0805  [CAP_C_0805]  (hidden comment: Capacitor NP)
C31  value 0.1uF  Voltage: 16V  Package: 0201  [CAP_C_0201]  (hidden comment: Capacitor NP)
C32  value 10uF  Voltage: 16V  Package: 0805  [CAP_C_0805]  (hidden comment: Capacitor NP)
C33  value 0.1uF  Voltage: 16V  Package: 0201  [CAP_C_0201]  (hidden comment: Capacitor NP)
C34  value 0.1uF  Voltage: 16V  Package: 0201  [CAP_C_0201]  (hidden comment: Capacitor NP)
C35  value 0.1uF  Voltage: 16V  Package: 0201  [CAP_C_0201]  (hidden comment: Capacitor NP)
C36  value 0.1uF  Voltage: 16V  Package: 0201  [CAP_C_0201]  (hidden comment: Capacitor NP)
C37  value 0.1uF  Voltage: 16V  Package: 0201  [CAP_C_0201]  (hidden comment: Capacitor NP)
C38  value 0.1uF  Voltage: 16V  Package: 0201  [CAP_C_0201]  (hidden comment: Capacitor NP)
C39  value 0.1uF  Voltage: 16V  Package: 0201  [CAP_C_0201]  (hidden comment: Capacitor NP)
C40  value 0.1uF  Voltage: 16V  Package: 0201  [CAP_C_0201]  (hidden comment: Capacitor NP)
C41  value 0.1uF  Voltage: 16V  Package: 0201  [CAP_C_0201]  (hidden comment: Capacitor NP)
C42  value 0.1uF  Voltage: 16V  Package: 0201  [CAP_C_0201]  (hidden comment: Capacitor NP)
C43  value 0.1uF  Voltage: 16V  Package: 0201  [CAP_C_0201]  (hidden comment: Capacitor NP)
C44  value 0.1uF  Voltage: 16V  Package: 0201  [CAP_C_0201]  (hidden comment: Capacitor NP)
C45  value 0.1uF  Voltage: 16V  Package: 0201  [CAP_C_0201]  (hidden comment: Capacitor NP)
C46  value 0.1uF  Voltage: 16V  Package: 0201  [CAP_C_0201]  (hidden comment: Capacitor NP)
C47  value 0.1uF  Voltage: 16V  Package: 0201  [CAP_C_0201]  (hidden comment: Capacitor NP)
C48  value 0.1uF  Voltage: 16V  Package: 0201  [CAP_C_0201]  (hidden comment: Capacitor NP)
C49  value 0.1uF  Voltage: 16V  Package: 0201  [CAP_C_0201]  (hidden comment: Capacitor NP)
C50  value 0.1uF  Voltage: 16V  Package: 0201  [CAP_C_0201]  (hidden comment: Capacitor NP)
C51  value 18pF  Voltage: 50V  Package: 0402  [CAP_C_0402]  (hidden comment: Capacitor NP)
C52  value 0.1uF  Voltage: 16V  Package: 0402  [CAP_C_0402]  (hidden comment: Capacitor NP)
C53  value 0.1uF  Voltage: 16V  Package: 0201  [CAP_C_0201]  (hidden comment: Capacitor NP)
C54  value 0.1uF  Voltage: 16V  Package: 0201  [CAP_C_0201]  (hidden comment: Capacitor NP)
C55  value 0.1uF  Voltage: 16V  Package: 0201  [CAP_C_0201]  (hidden comment: Capacitor NP)
C56  value 0.1uF  Voltage: 16V  Package: 0201  [CAP_C_0201]  (hidden comment: Capacitor NP)
C57  value 4.7uF  Voltage: 10V  Package: 0402  [CAP_C_0402]  (hidden comment: Capacitor NP)
C60  value 18pF  Voltage: 50V  Package: 0402  [CAP_C_0402]  (hidden comment: Capacitor NP)
C61  value 0.1uF  Voltage: 16V  Package: 0201  [CAP_C_0201]  (hidden comment: Capacitor NP)
C62  value 4.7uF  Voltage: 10V  Package: 0402  [CAP_C_0402]  (hidden comment: Capacitor NP)
C63  value 22pF  Voltage: 50V  Package: 0402  [CAP_C_0402]  (hidden comment: Capacitor NP)
C64  value 0.1uF  Voltage: 16V  Package: 0201  [CAP_C_0201]  (hidden comment: Capacitor NP)
C65  value 0.1uF  Voltage: 16V  Package: 0201  [CAP_C_0201]  (hidden comment: Capacitor NP)
C66  value 0.1uF  Voltage: 16V  Package: 0201  [CAP_C_0201]  (hidden comment: Capacitor NP)
C67  value 18pF  Voltage: 50V  Package: 0402  [CAP_C_0402]  (hidden comment: Capacitor NP)
C68  value 0.1uF  Voltage: 16V  Package: 0402  [CAP_C_0402]  (hidden comment: Capacitor NP)
C69  value 4.7uF  Voltage: 10V  Package: 0402  [CAP_C_0402]  (hidden comment: Capacitor NP)
C70  value 0.1uF  Voltage: 16V  Package: 0201  [CAP_C_0201]  (hidden comment: Capacitor NP)
C71  value 4.7uF  Voltage: 10V  Package: 0402  [CAP_C_0402]  (hidden comment: Capacitor NP)
C72  value 0.1uF  Voltage: 16V  Package: 0201  [CAP_C_0201]  (hidden comment: Capacitor NP)
C73  value 0.1uF  Voltage: 16V  Package: 0201  [CAP_C_0201]  (hidden comment: Capacitor NP)
C74  value 10pF  Voltage: 25V  Package: 0201  [CAP_C_0201]  (hidden comment: Capacitor NP)
C299  value 18pF  Voltage: 50V  Package: 0402  [CAP_C_0402]  (hidden comment: Capacitor NP)
R5  value 0R  [RES_C_0402]  (hidden comment: Resistor)
R66  value 10k  Package: 0402  Tolerance: 1%  [RES_C_0402]  (hidden comment: Resistor)
R67  value 16.9k  Package: 0402  Tolerance: 1%  [RES_C_0402]  (hidden comment: Resistor)
R68  value 0R  Package: 0402  [RES_C_0402]  (hidden comment: Resistor)
R69  value 0R  [RES_C_0402]  (hidden comment: Resistor)
R70  value 0R  [RES_C_0402]  (hidden comment: Resistor)
R71  value 0R  [RES_C_0402]  (hidden comment: Resistor)
R75  value 0R  Package: 0402  [RES_C_0402]  (hidden comment: Resistor)
R76  value 1R  Package: 0402  [RES_C_0402]  (hidden comment: Resistor)
R77  value 1R  Package: 0402  [RES_C_0402]  (hidden comment: Resistor)
R78  value 5.62K  Package: 0201  Tolerance: 1%  [RES_C_0201]  (hidden comment: Resistor)
R79  value 0R  Package: 0201  [RES_C_0201]  (hidden comment: Resistor)
R166  value 0R  Package: 0402  [RES_C_0402]  (hidden comment: Resistor)
R185  value 0R  Package: 0402  [RES_C_0402]  (hidden comment: Resistor)
U4  value ATSAMA5D27C  [LFBGA-289_P0.8_14x14x1.4]  (hidden comment: ATSAMA5D27C LFBGA-289)  (parts F,G of 7)
Y1  value 32.768kHz  Manufacturer Part Number 1: NX2012SA-32.768K-STD-MUB-1  [CRYSTAL_NX2012SA]  (hidden comment: Crystal 2 Pins)
Y3  value 12MHz  Manufacturer Part Number 1: DSC1001DL5-012.0000  [DFN-4_2.5x2]  (hidden comment: DSC10xx DFN-4)
Y4  value 12Mhz  Manufacturer Part Number 2: CX3225SB12000H0PSTC1  [CRYSTAL_TSX-3225_L3.2W2.5H0.6]  (hidden comment: Crystal 4 pins 1-3)

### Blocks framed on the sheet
MPU configuration: C63 C68 C74 R66-R68 R75 R78 U4
MPU Power Supply and Decoupling: C29-C50 C53-C57 C61 C62 C64-C66 C69-C73 R76 R77 R79 U4
32kHz Clock: C51 C299 Y1
12MHz Clock: C52 C60 C67 R5 R69-R71 R166 R185 Y3 Y4

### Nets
3V3: C52.2 R166.1 Y3.4(VDD)
GND: C29.1 C30.1 C31.1 C32.1 C33.1 C34.1 C35.1 C36.1 C37.1 C38.1 C39.1 C40.1 C41.1 C42.1 C43.1 C44.1 C45.1 C46.1 C47.1 C48.1 C49.1 C50.1 C51.1 C52.1 C53.1 C54.1 C55.1 C56.1 C57.1 C60.1 C61.1 C62.1 C63.1 C64.1 C65.1 C66.1 C67.1 C68.2 C70.1 C72.1 C73.1 C299.1 R5.1 R66.2 R67.1 R76.1 R77.1 R79.2 U4.D14(GNDDDR_1) U4.E7(GNDCORE_1) U4.E9(GNDCORE_2) U4.E11(GNDDDR_2) U4.E12(GNDDDR_3) U4.E14(GNDDDR_4) U4.F6(GNDIOP0_1) U4.F9(GNDPIO2) U4.G4(GNDISC) U4.G7(GNDIOP0_2) U4.H4(GNDCORE_3) U4.H14(GNDDDR_5) U4.J14(GNDDDR_6) U4.K5(GNDANA_2) U4.K12(GNDCORE_4) U4.L3(GNDANA_1) U4.L14(GNDDDR_7) U4.M5(GNDCORE_5) U4.M9(GNDCORE_6) U4.M13(GNDIOP1_1) U4.N6(GNDBU) U4.P14(GNDIOP1_2) U4.R7(GNDUTMIC) U4.R11(GNDSDMMC) U4.T4(GNDAUDIOPLL) U4.T5(GNDPLL) U4.T6(GNDOSC) U4.U5(GNDPLLA) Y3.2(GND) Y4.2 Y4.4
GNDUTMII: C74.1 R78.1 R79.1 U4.P9(GNDUTMII)
VDDANA: C31.2 C34.2 R68.1 U4.K3(VDDANA_1) U4.L5(VDDANA_2)
VDDAUDIOPLL: C57.2 C61.2 U4.T3(VDDAUDIOPLL)
VDDBU: C56.2 R75.1 U4.N7(VDDBU)
VDDCORE: C29.2 C32.2 C35.2 C39.2 C42.2 C44.2 C48.2 C53.2 U4.D7(VDDCORE_1) U4.D9(VDDCORE_2) U4.H3(VDDCORE_3) U4.K13(VDDCORE_4) U4.N5(VDDCORE_5) U4.N9(VDDCORE_6)
VDDFUSE: C55.2 U4.M12(VDDFUSE)
VDDHSIC: C47.2 U4.R9(VDDHSIC)
VDDIODDR: C30.2 C33.2 C36.2 C40.2 C43.2 C45.2 C49.2 C54.2 U4.D11(VDDDDR_1) U4.D12(VDDDDR_2) U4.D15(VDDDDR_3) U4.E15(VDDDDR_4) U4.H15(VDDDDR_5) U4.J15(VDDDDR_6) U4.L15(VDDDDR_7)
VDDIOP0: C37.2 C41.2 U4.E6(VDDIOP0_1) U4.F7(VDDIOP0_2)
VDDIOP1: C46.2 C50.2 U4.N13(VDDIOP1_1) U4.R14(VDDIOP1_2)
VDDIOP2: C38.2 U4.F10(VDDIOP2)
VDDISC: C73.2 U4.F4(VDDISC)
VDDOSC: C71.2 C72.2 U4.T7(VDDOSC)
VDDPLLA: C69.2 C70.2 U4.U4(VDDPLLA)
VDDSDHC: C66.2 U4.P11(VDDSDMMC)
VDDUTMIC: C62.2 C65.2 U4.P7(VDDUTMIC)
VDDUTMII: C64.2 U4.P8(VDDUTMII)
HHSA_n: U4.R8(HHSDMA) ; off-sheet HHSA_n
HHSA_p: U4.T8(HHSDPA) ; off-sheet HHSA_p
HHSB_n: U4.U9(HHSDMB) ; off-sheet HHSB_n
HHSB_p: U4.U8(HHSDPB) ; off-sheet HHSB_p
HSIC_DATA: U4.T9(HHSDPDATC) ; off-sheet HSIC_DATA
HSIC_STROBE: U4.U10(HHSDMSTRC) ; off-sheet HSIC_STROBE
NRST: U4.U2(NRST) ; off-sheet NRST
PIOBU1: U4.N8(PIOBU1) ; off-sheet PIOBU1
PIOBU2: U4.R2(PIOBU2) ; off-sheet PIOBU2
PIOBU3: U4.R5(PIOBU3) ; off-sheet PIOBU3
PIOBU4: U4.R4(PIOBU4) ; off-sheet PIOBU4
PIOBU5: U4.P5(PIOBU5) ; off-sheet PIOBU5
PIOBU6: U4.P6(PIOBU6) ; off-sheet PIOBU6
PIOBU7: U4.M8(PIOBU7) ; off-sheet PIOBU7
PIOUB0: R185.1 U4.R3(PIOBU0)
SHDN: U4.R1(SHDN) ; off-sheet SHDN
WAKE_UP: U4.P4(WKUP) ; off-sheet WAKE_UP
Xin: R69.2 R70.2 U4.U7(XIN)
Xin_32: C51.2 U4.P1(XIN32) Y1.2(Osc2)
Xout: R5.2 R71.2 U4.U6(XOUT)
Xout_32: C299.2 U4.P2(XOUT32) Y1.1(Osc1)
NetC60_2: C60.2 R70.1 Y4.1
NetC63_2: C63.2 R67.2 U4.T10(SDCAL)
NetC67_2: C67.2 R71.1 Y4.3
NetC68_1: C68.1 R68.2 U4.M6(ADVREF)
NetC69_1: C69.1 R76.2
NetC71_1: C71.1 R77.2
NetC74_2: C74.2 R78.2 U4.R6(VBG)
NetR66_1: R66.1 U4.P3(TST)
NetR69_1: R69.1 Y3.3(OUT)
NetR75_2: R75.2 U4.T2(JTAGSEL)
NetR166_2: R166.2 R185.2 Y3.1(~{STB})

Not connected (* = marked no-connect by the designer): U4 N4(RXD)* T1(COMPP)* U1(COMPN)* U3(CLK_AUDIO)*

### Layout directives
differential pair; differential pair class DIFF90; net class DIFF90; rule Matched Net Lengths [Tolerance = 10mil]: HHSA_n, HHSA_p, HHSB_n, HHSB_p

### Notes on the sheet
- HSIC_DATA
- (near R78) HSIC_STROBE
- place R&C
- as close
- as possible
- User Button

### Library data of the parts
?#4 = Title Block B
C29 C30 C32 = CAP1323: Capacitor; Manufacturer 1: Taiyo Yuden; Manufacturer Part Number 1: EMK212BB7106MG-T; Description_: CAP CER 10uF 16V 20% X7R SMD 0805; Dev Tools Status: Production; Tolerance: 20%; Temperature Coeffcient: X7R; Type: Ceramic; Owner: Rodger Griffith; Populated: YES
C31 C33-C50 C53-C56 C61 C64-C66 C70 C72 C73 = CAP1559: Capacitor; Manufacturer 1: Murata Electronics North America; Manufacturer Part Number 1: GRM033R61C104KE84D; Description_: CAP CER 0.1µF 16V 10% X5R SMD 0201; Dev Tools Status: Design; Tolerance: 10%; Temperature Coeffcient: X5R; Type: Ceramic; Owner: Gabor Bihari; Populated: YES
C51 C299 = CAP1091: Capacitor; Manufacturer 1: Murata; Manufacturer Part Number 1: GRM1555C1H180JA01D; Description_: CAP CER 18pF 50V 5% C0G SMD 0402; Dev Tools Status: Production; Tolerance: 5%; Temperature Coeffcient: C0G; Type: Ceramic; Owner: Tad Ahlvers; Populated: YES
C52 C68 = CAP1033: as C2 on sheet 01 - Power Supply
C57 C62 C69 C71 = CAP1684: as C11 on sheet 01 - Power Supply
C60 C67 = CAP1091: Capacitor; Manufacturer 1: Murata; Manufacturer Part Number 1: GRM1555C1H180JA01D; Description_: CAP CER 18pF 50V 5% C0G SMD 0402; Dev Tools Status: Production; Tolerance: 5%; Temperature Coeffcient: C0G; Type: Ceramic; Owner: Tad Ahlvers; Populated: DNP
C63 = CAP1042: Capacitor; Manufacturer 1: Murata; Manufacturer Part Number 1: GRM1555C1H220JZ01D; Description_: CAP CER 22pF 50V 5% NP0 SMD 0402; Dev Tools Status: Production; Tolerance: 5%; Temperature Coeffcient: NP0; Type: Ceramic; Owner: Sompoch Loboonlert; Populated: Yes
C74 = CAP1453: Capacitor; Manufacturer 1: TDK Corporation; Manufacturer Part Number 1: C0603C0G1E100D030BA; Description_: CAP CER 10pF 25V 0.5pF C0G SMD 0201; Dev Tools Status: Design; Tolerance: 0.5pF; Temperature Coeffcient: C0G; Type: Ceramic; Owner: Gabor Bihari; Populated: YES
R5 R68 R69 R185 = RSMT1040: Manufacturer 1: Yageo; Manufacturer Part Number 1: RC0402JR-070RL; Description_: RES TKF 0R 1/16W SMD 0402; Dev Tools Status: Production; Power: 1/16W; Owner: Sompoch Loboonlert; Populated: Yes
R66 = RSMT1019: Manufacturer 1: Panasonic; Manufacturer Part Number 1: ERJ-2RKF1002X; Description_: RES TKF 10k 1% 1/10W SMD 0402; Dev Tools Status: Production; Voltage: 50V; Temperature Coeffcient: 100ppm/C; Power: 1/10W; Owner: Brent Lanphear; Populated: Yes
R67 = RES1623: Manufacturer 1: Samsung; Manufacturer Part Number 1: RC1005F1692CS; Description_: RES TKF 16.9k 1% 1/16W SMD 0402; Dev Tools Status: Production; Voltage: 50V; Power: 1/16W; Owner: Mike Ragsdale; Populated: YES
R70 R71 R75 R166 = RSMT1040: as R7 on sheet 01 - Power Supply
R76 R77 = RES1659: Manufacturer 1: Yageo                                                                                               Yageo; Manufacturer Part Number 1: RC0402FR-071RL; Tolerance: 1%; Description_: RES TKF 1R 1% 1/16W SMD 0402; Dev Tools Status: Design; Voltage: 50V; Temperature Coeffcient: 200ppm/°C; Current: 1A; Power: 1/16W; Owner: Jose Garcia; Populated: YES
R78 = RES2053: Manufacturer 1: Yageo; Manufacturer Part Number 1: RC0201FR-075K62L; Description_: RES TKF 5.62K 1% 1/20W SMD 0201; Dev Tools Status: Design; Temperature Coeffcient: 200ppm/C; Power: 1/20W; Owner: Ilie Galan; Populated: YES
R79 = RES1581: Manufacturer 1: Panasonic Electronic Components; Manufacturer Part Number 1: ERJ-1GE0R00C; Description_: RES TKF 0R 0.05W SMD 0201; Dev Tools Status: Design; Current: 0.5A; Owner: Gabor Bihari; Populated: YES
U4 = MIC7216: Manufacturer 1: Microchip Technology; Manufacturer Part Number 1: ATSAMA5D27C-CU; Description_: MCHP MPU 32-BIT Cortex®-A5 500MHz ATSAMA5D27C-CU LFBGA-289; MAPS Description: BGA GREEN, IND TEMP,MRLC; Dev Tools Status: Design; Owner: Bogdan Popescu; MPC: 92U037AMBC05; LeadContent: Pb-FREE; TempRange: -40C to +85C; Stage: REL; PackageWidth: 14x14x1.4mm; PackingMedia: TRAY; ForceMinOrderQtyMult: False; MinOrderQty: 1; LeadCount: 289; Program Memory KBytes: 0; Ram: 131072; IOPins: 128; MaxSpeed: 500; OscillatorMHz: 32kHz, 12MHz; ADC Channels: 12; USART: 10; SPI: 7; CAN: 2; USBChannels: 3; Input Capture: 6; mtrlcntrlpwmchannels: 8; CapTouchCH: 16; DigitalTimerQty_16bit: 4; Populated: YES
Y1 = OSC1092: Crystal; Manufacturer 1: NDK; Description_: CRYSTAL 32.768kHz 12.5pF SMD NX2012SA; Dev Tools Status: Production; Owner: Jamus Griego; Tolerance: ±20ppm; Load Capacitance: 12.5pF; Populated: YES
Y3 = MIC8807: Manufacturer 1: Microchip Technology; Description_: MCHP CLOCK OSCILLATOR SINGLE 12MHz DSC1001DL5-012.0000 SMD-2520; Dev Tools Status: Design; Owner: Ilie Galan; Populated: YES
Y4 = OSC1067: Crystal; Manufacturer 1: AVX Corp/Kyocera Corp; Manufacturer Part Number 1: CX3225SB12000H0FLJCC; Description_: CRYSTAL 12MHz 12pF SMD L3.2W2.5H0.6; Dev Tools Status: Production; Owner: Duane Burt; Load Capacitance: 12pF; Populated: DNP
